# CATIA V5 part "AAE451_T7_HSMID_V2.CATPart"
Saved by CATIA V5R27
Part number: HorizontalStab
Bounding box of the stored display mesh (mm): x -280 to 13.7, y -18.492 to 4.512, z -125 to 125
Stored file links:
  W:\AAE 451\AAE451_T7_TailAssembly_V2\AAE451_T7_HSMID_V2.CATPart
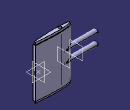
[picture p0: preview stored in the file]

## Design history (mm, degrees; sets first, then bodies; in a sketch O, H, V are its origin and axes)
Set1 "GeometryFromExcel"
  Point1: (1, 0.001, 0)
  Point2: (0.95, 0.0067, 0)
  Point3: (0.9, 0.0121, 0)
  Point4: (0.8, 0.0219, 0)
  Point5: (0.7, 0.0305, 0)
  Point6: (0.6, 0.038, 0)
  Point7: (0.5, 0.0441, 0)
  Point8: (0.4, 0.0484, 0)
  Point9: (0.3, 0.05, 0)
  Point10: (0.25, 0.0495, 0)
  Point11: (0.2, 0.0478, 0)
  Point12: (0.15, 0.0445, 0)
  Point13: (0.1, 0.039, 0)
  Point14: (0.075, 0.035, 0)
  Point15: (0.05, 0.0296, 0)
  Point16: (0.025, 0.0218, 0)
  Point17: (0.0125, 0.0158, 0)
  Point18: (0, 0, 0)
  Point19: (0.0125, -0.0158, 0)
  Point20: (0.025, -0.0218, 0)
  Point21: (0.05, -0.0296, 0)
  Point22: (0.075, -0.035, 0)
  Point23: (0.1, -0.039, 0)
  Point24: (0.15, -0.0445, 0)
  Point25: (0.2, -0.0478, 0)
  Point26: (0.25, -0.0495, 0)
  Point27: (0.3, -0.05, 0)
  Point28: (0.4, -0.0484, 0)
  Point29: (0.5, -0.0441, 0)
  Point30: (0.6, -0.038, 0)
  Point31: (0.7, -0.0305, 0)
  Point32: (0.8, -0.0219, 0)
  Point33: (0.9, -0.0121, 0)
  Point34: (0.95, -0.0067, 0)
  Point35: (1, -0.001, 0)
  Point36: (1, 0.001, 0)
  Point37: (0.95, 0.0067, 0)
  Point38: (0.9, 0.0121, 0)
  Point39: (0.8, 0.0219, 0)
  Point40: (0.7, 0.0305, 0)
  Point41: (0.6, 0.038, 0)
  Point42: (0.5, 0.0441, 0)
  Point43: (0.4, 0.0484, 0)
  Point44: (0.3, 0.05, 0)
  Point45: (0.25, 0.0495, 0)
  Point46: (0.2, 0.0478, 0)
  Point47: (0.15, 0.0445, 0)
  Point48: (0.1, 0.039, 0)
  Point49: (0.075, 0.035, 0)
  Point50: (0.05, 0.0296, 0)
  Point51: (0.025, 0.0218, 0)
  Point52: (0.0125, 0.0158, 0)
  Point53: (0, 0, 0)
  Point54: (0.0125, -0.0158, 0)
  Point55: (0.025, -0.0218, 0)
  Point56: (0.05, -0.0296, 0)
  Point57: (0.075, -0.035, 0)
  Point58: (0.1, -0.039, 0)
  Point59: (0.15, -0.0445, 0)
  Point60: (0.2, -0.0478, 0)
  Point61: (0.25, -0.0495, 0)
  Point62: (0.3, -0.05, 0)
  Point63: (0.4, -0.0484, 0)
  Point64: (0.5, -0.0441, 0)
  Point65: (0.6, -0.038, 0)
  Point66: (0.7, -0.0305, 0)
  Point67: (0.8, -0.0219, 0)
  Point68: (0.9, -0.0121, 0)
  Point69: (0.95, -0.0067, 0)
  Point70: (1, -0.001, 0)
  Curve1: Elements (Point36; Point37; Point38; Point39; Point40; Point41; Point42; Point43; Point44; Point45; Point46; Point47; Point48; Point49; Point50; Point51; Point52; Point53; Point54; Point55; Point56; Point57; Point58; Point59; Point60; Point61; Point62; Point63; Point64; Point65; Point66; Point67; Point68; Point69; Point70)
  Sketch1 on xy-plane, origin (0, 0, 0), H (1, 0, 0), V (0, 1, 0)
    projected curve E1 from edge of Curve1
    point P1 (1, 0.0011)
    line L1 (1, 0.0011) -> (1, -0.001)
    point P3 (1, 0.001)
    point P4 (1, -0.001)
    reference projected point E2 (1, 0.001) from Point1
    reference projected point E3 (1, -0.001) from Point35
    coincidence: P3 E2, P4 E3, P1 P3
Body1 (main body)
  Pad1: profile Sketch1, direction (0, 0, 1), length 1.5215, mirrored extent
  Scaling1: ToTransfor Pad1, Reference Point40, Ratio 230
  Sketch2 on zx-plane, origin (0, 0, 0), H (-1, 0, 0), V (0, 0, 1)
    line L1 (-74.5369, 349.945) -> (165.4631, 349.945)
    line L2 (165.4631, 349.945) -> (165.4631, 115)
    line L3 (165.4631, 115) -> (-74.5369, 115)
    line L4 (-74.5369, 115) -> (-74.5369, 349.945)
    line L5 (-74.5369, -115) -> (165.4631, -115)
    line L6 (165.4631, -115) -> (165.4631, -349.945)
    line L7 (165.4631, -349.945) -> (-74.5369, -349.945)
    line L8 (-74.5369, -349.945) -> (-74.5369, -115)
    reference projected line E1 (-69.7, 349.945) -> (160.3, 349.945) from edge [face of Pad1 from Sketch1.E1 | end face of Pad1]
    reference projected line E2 (-69.7, -349.945) -> (160.3, -349.945) from edge [start face of Pad1 | face of Pad1 from Sketch1.E1]
    distance L3 L5 = 230
    distance L2 L4 = 240
    horizontal: L1 H, L3 H, L5 H, L7 H
    vertical: L2 V, L4 V, L6 V, L8 V
    symmetry: L3 L5 H, L8 L4 H, L2 L6 H
    coincidence: L1 E1, L7 E2
  Pocket1: profile Sketch2, direction (0, -1, 0), through (limit type 6), opposite side through (limit type 6)
  Sketch3 on face of Pocket1 from Sketch2.L3, origin (0, 0, 115), H (1, 0, 0), V (0, 1, 0)
    line L1 (13.7, -12.9188) -> (13.7, -1.064)
    point P1 (13.7, -12.9188)
    point P2 (13.7, -1.064)
    reference projected curve E1 from edge [face of Pad1 from Sketch1.E1 | face of Pocket1 from Sketch2.L3]
    reference projected curve E2 from edge [face of Pad1 from Sketch1.E1 | face of Pocket1 from Sketch2.L3]
    projected curve E3 from edge [face of Pad1 from Sketch1.E1 | face of Pocket1 from Sketch2.L3]
    projected curve E4 from edge [face of Pad1 from Sketch1.E1 | face of Pocket1 from Sketch2.L3]
    projected curve E5 from edge [face of Pad1 from Sketch1.E1 | face of Pocket1 from Sketch2.L3]
    point P3 (69.7, -6.7499)
    line L2 (69.7, -6.7499) -> (69.7, -7.2329)
    distance L1 P3 = 56
    coincidence: P1 E1, P2 E2
    vertical: L1 V
  Pocket2: profile Sketch3, direction (0, 0, -1), through (limit type 6)
  Shell1: ExtOffset 0, Face (face of Pocket1 from Sketch2.L3; face of Pocket1 from Sketch2.L5), IntOffset 1.8
  Sketch4 on face of Pocket1 from Sketch2.L3, origin (0, 0, 115), H (1, 0, 0), V (0, 1, 0)
    projected curve E1 from edge [face of Shell1 | face of Pocket1 from Sketch2.L3]
    projected line E2 (11.9, -11.2688) -> (11.9, -2.714) from edge [face of Pocket1 from Sketch2.L3 | face of Shell1]
  Pad2: profile Sketch4, direction (0, 0, 1), length 10, opposite side length 10
  Plane1: type Offset, RefPlane yz-plane, Offset 120, reversed
  Mirror1: of Pad2, about xy-plane
  Sketch5 on Plane1, origin (-120, 0, 0), H (0, 1, 0), V (0, 0, 1)
    circle A1 centre (-7, 26) radius 6.85
    point P1 (-7, 26)
    circle A2 centre (-7, -26) radius 6.85
    point P2 (-7, -26)
    radius A1 = 6.85
    distance P1 P2 = 52
    distance V P1 = 7
    symmetry: A2 A1 H
  Pocket3: profile Sketch5, direction (-1, 0, 0), through (limit type 3)
  Sketch6 on Plane1, origin (-120, 0, 0), H (0, 1, 0), V (0, 0, 1)
    projected circle E1 centre (-7, 26) radius 6.85 from edge [face of Pocket3 from Sketch5.A1 | face of Pad1 from Sketch1.E1]
    projected circle E2 centre (-7, -26) radius 6.85 from edge [face of Pocket3 from Sketch5.A2 | face of Pad1 from Sketch1.E1]
    circle A1 centre (-7, 26) radius 10
    circle A2 centre (-7, -26) radius 10
    radius A1 = 10
    radius A2 = 10
    concentricity: A2 E2, A1 E1
  Pad3: profile Sketch6, direction (-1, 0, 0), up to the existing solid (limit type 2)
  Sketch7 on Plane1, origin (-120, 0, 0), H (0, 1, 0), V (0, 0, 1)
    projected circle E1 centre (-7, 26) radius 6.85 from edge [face of Pocket3 from Sketch5.A1 | face of Pad1 from Sketch1.E1]
    projected circle E2 centre (-7, -26) radius 6.85 from edge [face of Pad1 from Sketch1.E1 | face of Pocket3 from Sketch5.A2]
  Pad4: profile Sketch7, direction (-1, 0, 0), length 5
  Sketch8 on end face of Pad2, origin (0, 0, 125), H (1, 0, 0), V (0, 1, 0)
    circle A1 centre (-110, -7) radius 6.85
    point P1 (-110, -7)
    reference intersected line E1 through (-120, 0) direction (0, 1) from Plane1
    distance P1 E1 = 10
    distance P1 H = 7
    radius A1 = 6.85
  Pocket4: profile Sketch8, direction (0, 0, -1), through (limit type 3)
  Sketch9 on face of Pocket1 from Sketch2.L3, origin (0, 0, 115), H (1, 0, 0), V (0, 1, 0)
    projected circle E1 centre (-110, -7) radius 6.85 from edge [end face of Pad2 | face of Pocket4 from Sketch8.A1]
    circle A1 centre (-110, -7) radius 10
    radius A1 = 10
    concentricity: E1 A1
  Pad5: profile Sketch9, direction (0, 0, -1), length 230
  Plane2: type Offset, RefPlane Plane1, Offset 60, reversed
  Sketch10 on Plane2, origin (-180, 0, 0), H (0, 1, 0), V (0, 0, 1)
    projected circle E1 centre (-7, 26) radius 6.85 from edge [end face of Pad4 | face of Pad3 from Sketch6.E1]
    projected circle E2 centre (-7, -26) radius 6.85 from edge [face of Pocket3 from Sketch5.A2 | face of Pad1 from Sketch1.E1]
    circle A1 centre (-7, 26) radius 10
    circle A2 centre (-7, -26) radius 10
    radius A1 = 10
    concentricity: A1 E1, A2 E2
    symmetry: A1 A2 H
  Pad6: profile Sketch10, direction (1, 0, 0), up to the existing solid (limit type 2), opposite side length 100
  Sketch11 on face of Pocket2 from Sketch3.L1, origin (13.7, 0, 0), H (0, 1, 0), V (0, 0, 1)
    line L1 (-7.4914, 8) -> (-6.4914, 8)
    line L2 (-6.4914, 8) -> (-6.4914, -8)
    line L3 (-6.4914, -8) -> (-7.4914, -8)
    line L4 (-7.4914, -8) -> (-7.4914, 8)
    construction line L5 (-6.9914, -9.0955) -> (-6.9914, 10.5019)
    reference projected line E1 (-12.9188, 115) -> (-12.9188, -115) from edge [face of Pad1 from Sketch1.E1 | face of Pocket2 from Sketch3.L1]
    reference projected line E2 (-1.064, 115) -> (-1.064, -115) from edge [face of Pocket2 from Sketch3.L1 | face of Pad1 from Sketch1.E1]
    length L1 = 1
    length L2 = 16
    horizontal: L1 H, L3 H
    vertical: L2 V, L4 V
    symmetry: L1 L3 H, L4 L2 L5, E1 E2 L5
  Pocket5: profile Sketch11, direction (-1, 0, 0), length 13.7
  Sketch12 on face of Pocket2 from Sketch3.L1, origin (13.7, 0, 0), H (0, 1, 0), V (0, 0, 1)
    projected line E1 (-6.4914, -8) -> (-6.4914, 8) from edge [face of Pocket2 from Sketch3.L1 | face of Pocket5 from Sketch11.L2]
    projected line E2 (-7.4914, 8) -> (-7.4914, -8) from edge [face of Pocket2 from Sketch3.L1 | face of Pocket5 from Sketch11.L4]
    projected line E3 (-6.4914, 8) -> (-7.4914, 8) from edge [face of Pocket2 from Sketch3.L1 | face of Pocket5 from Sketch11.L1]
    projected line E4 (-7.4914, -8) -> (-6.4914, -8) from edge [face of Pocket2 from Sketch3.L1 | face of Pocket5 from Sketch11.L3]
    line L1 (-8.4914, 9) -> (-5.4914, 9)
    line L2 (-5.4914, 9) -> (-5.4914, -9)
    line L3 (-5.4914, -9) -> (-8.4914, -9)
    line L4 (-8.4914, -9) -> (-8.4914, 9)
    distance L4 E2 = 1
    distance E1 L2 = 1
    distance E3 L1 = 1
    distance L3 E4 = 1
    horizontal: L1 H, L3 H
    vertical: L2 V, L4 V
  Pad7: profile Sketch12, direction (-1, 0, 0), length 13.7
  Sketch13 on end face of Pad2, origin (0, 0, 125), H (1, 0, 0), V (0, 1, 0)
    projected curve E1 from edge [face of Pad2 from Sketch4.E1 | end face of Pad2]
    projected line E2 (11.9, -11.2688) -> (11.9, -2.714) from edge [face of Pad2 from Sketch4.E2 | end face of Pad2]
    frozenspline C1
    frozenspline C2
    line L1 (10.9, -10.3514) -> (10.9, -3.6314)
  Pocket6: profile Sketch13, direction (0, 0, -1), length 10
  Mirror2: of Pocket6, about xy-plane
